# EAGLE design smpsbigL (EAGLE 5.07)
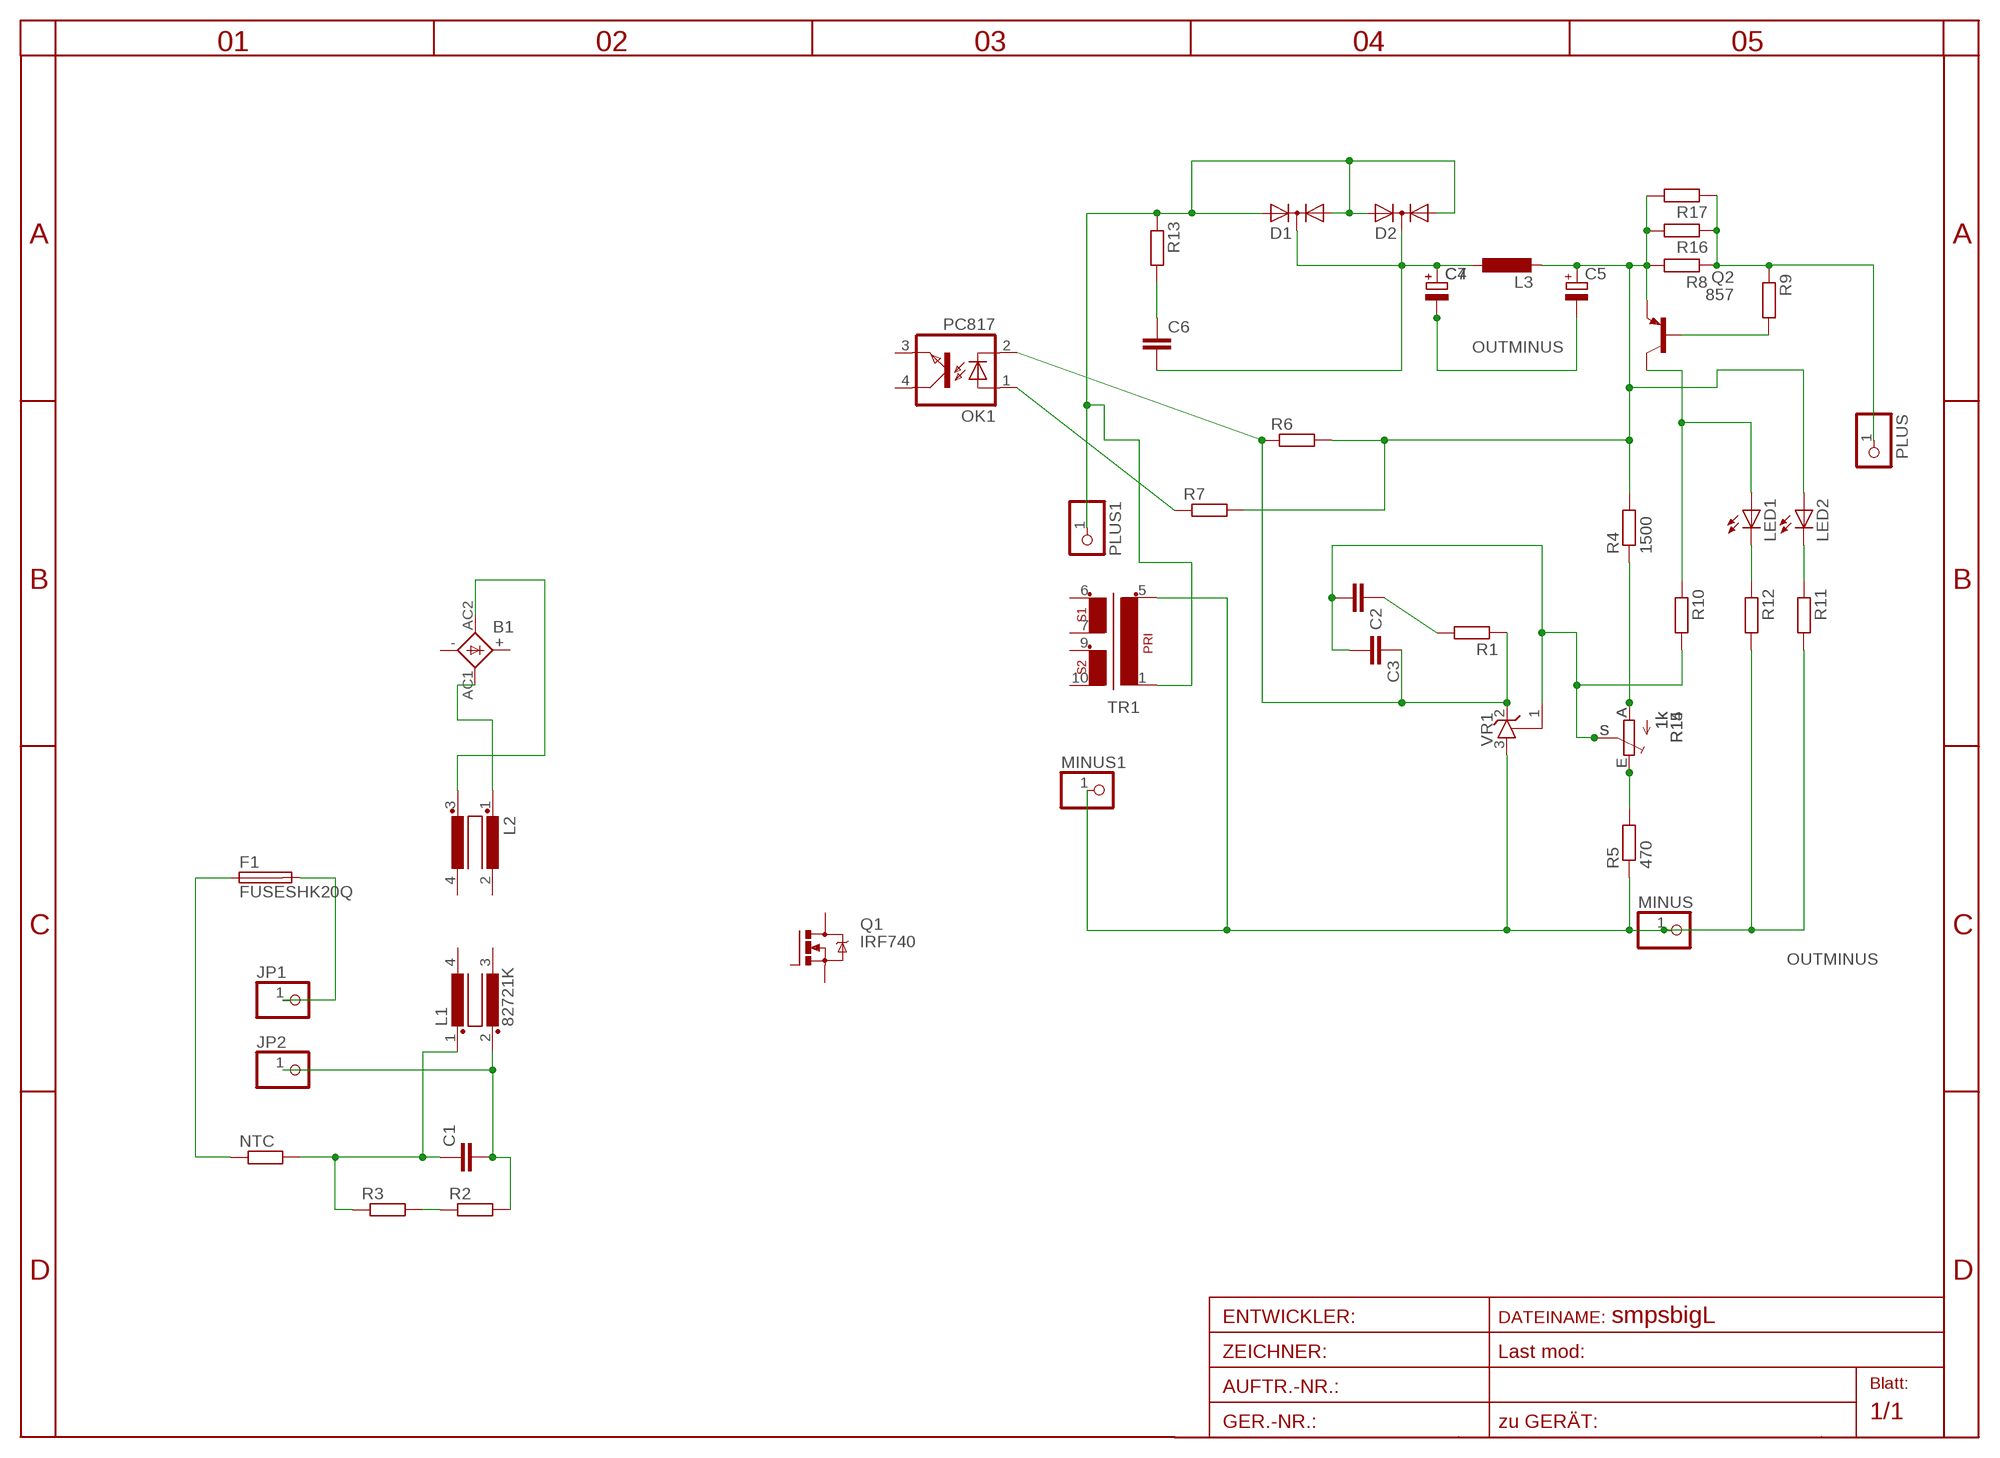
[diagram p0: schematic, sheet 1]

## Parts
B1  KBL  [KBL]
C1  C-EU150-084X183  [C150-084X183]
C2  C-EUC0805  [C0805]
C3  C-EUC0805  [C0805]
C4  CPOL-EUE5-8.5  [E5-8,5]
C5  CPOL-EUE5-8.5  [E5-8,5]
C6  C-EUC1206  [C1206]
C7  CPOL-EUE2.5-7  [E2,5-7]
D1  DIODE-2AC|CAIW220V  [IW220ABS]
D2  DIODE-2AC|CAIW220V  [IW220ABS]
F1  FUSESHK20Q  [SHK20Q]
JP1  PINHD-1X12MM2  [1X2MM2]
JP2  PINHD-1X12MM2  [1X2MM2]
L1  82721K  [82721K]
L2  R1405VB1  [B1]
L3  L-EUOPEN  [OPEN5]
LED1  LED3MM  [LED3MM]
LED2  LED3MM  [LED3MM]
MINUS  PINHD-1X12MM2  [1X2MM2]
MINUS1  PINHD-1X11X0.4  [1X01]
NTC  R-EU_0204/7  [0204/7]
OK1  PC817  [DIL04]
PLUS  PINHD-1X12MM2  [1X2MM2]
PLUS1  PINHD-1X11X0.4  [1X01]
Q1  IRF740  [TO220BV]
Q2  857  BC857ASMD  [SOT23-BEC]
R1  R-EU_R0805  [R0805]
R2  R-EU_R1206  [R1206]
R3  R-EU_R1206  [R1206]
R4  1500  R-EU_R0805  [R0805]
R5  470  R-EU_R0805  [R0805]
R6  R-EU_R0805  [R0805]
R7  R-EU_R0805  [R0805]
R8  R-EU_R3216  [R3216]
R9  R-EU_R0805  [R0805]
R10  R-EU_R0805  [R0805]
R11  R-EU_R0805  [R0805]
R12  R-EU_R0805  [R0805]
R13  R-EU_R1206  [R1206]
R14  1k  TRIM_EU-S64W  [S64W]
R15  1k  TRIM_EU-CA6V  [CA6V]
R16  R-EU_R2010  [R2010]
R17  R-EU_R1206  [R1206]
TR1  EE20-2  [EE30GREEN]
VR1  TL431CLPSOT23  [SOT23]

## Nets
A: R4.1 R14.A R15.A
C1: LED1.A Q2.C R10.1
CPLUS: C4.+ C6.2 C7.+ D1.C D2.C L3.1
E: R5.2 R14.E R15.E
N$1: C1.2 JP2.1 L1.2 R2.2
N$2: C1.1 L1.1 NTC.2 R3.1
N$3: F1.2A JP1.1
N$6: R2.1 R3.2
N$7: B1.AC2(AC1) L2.3
N$8: B1.AC1(AC2) L2.1
N$9: F1.1A NTC.1
N$11: C3.1 OK1.2(C) R1.1 R6.1 VR1.2(C)
N$12: OK1.1(A) R7.1
N$13: C2.1 R1.2
N$16: Q2.B R9.2
N$21: LED1.K(C) R12.1
N$23: LED2.K(C) R11.1
N$27: C6.1 R13.2
OUTMINUS: C4.- C5.- C7.- MINUS1.1 MINUS.1 R5.1 R11.2 R12.2 TR1.5 VR1.3(A)
OUTPLUS: PLUS.1 R8.1 R9.1 R16.1 R17.1
PLUS2: C5.+ L3.2 LED2.A Q2.E R4.2 R6.2 R7.2 R8.2 R16.2 R17.2
S: C2.2 C3.2 R10.2 R14.S R15.S VR1.1(R)
TOUT: D1.A1 D1.A2 D2.A1 D2.A2 PLUS1.1 R13.1 TR1.1
Unconnected: B1.+ B1.- L1.3 L1.4 L2.2 L2.4 OK1.3(EMIT) OK1.4(COL) Q1.D Q1.G Q1.S TR1.6 TR1.7 TR1.9 TR1.10

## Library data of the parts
B1 = rectifier:KBL: DIOTEC RECTIFIER
C1-C3 C6 = rcl:C-EU: CAPACITOR, European symbol
C4 C5 C7 = rcl:CPOL-EU: POLARIZED CAPACITOR, European symbol
D1 D2 = diode:DIODE-2AC|CA: Dual DIODE Anode-Cathode|Cathode-Anode
F1 = fuse:FUSE: Fuse
JP1 JP2 MINUS MINUS1 PLUS PLUS1 = pinhead:PINHD-1X1: PIN HEADER
L1 = inductors:82721K: FILTER
L2 = inductor-nkl:R1405V: Übertrager (verlustarm) bis typ. 400kHz Power transformer (low loss) up to typ. 400kHz
L3 = rcl:L-EU: INDUCTOR, European symbol
LED1 LED2 = led:LED: LED
NTC R1-R13 R16 R17 = rcl:R-EU_: RESISTOR, European symbol
OK1 = optocoupler:PC817: SHARP OPTO COUPLER
Q1 = transistor-power:IRF740: N-CHANNEL MOS FET
Q2 = transistor-pnp:BC857*: PNP Transistror
R14 R15 = pot:TRIM_EU-: POTENTIOMETER
TR1 = trafo:EE20-2: TRANSFORMER 1 primary winding, 2 secondary windings ERA
VR1 = v-reg:TL431CLP: VOLTAGE REGULATOR

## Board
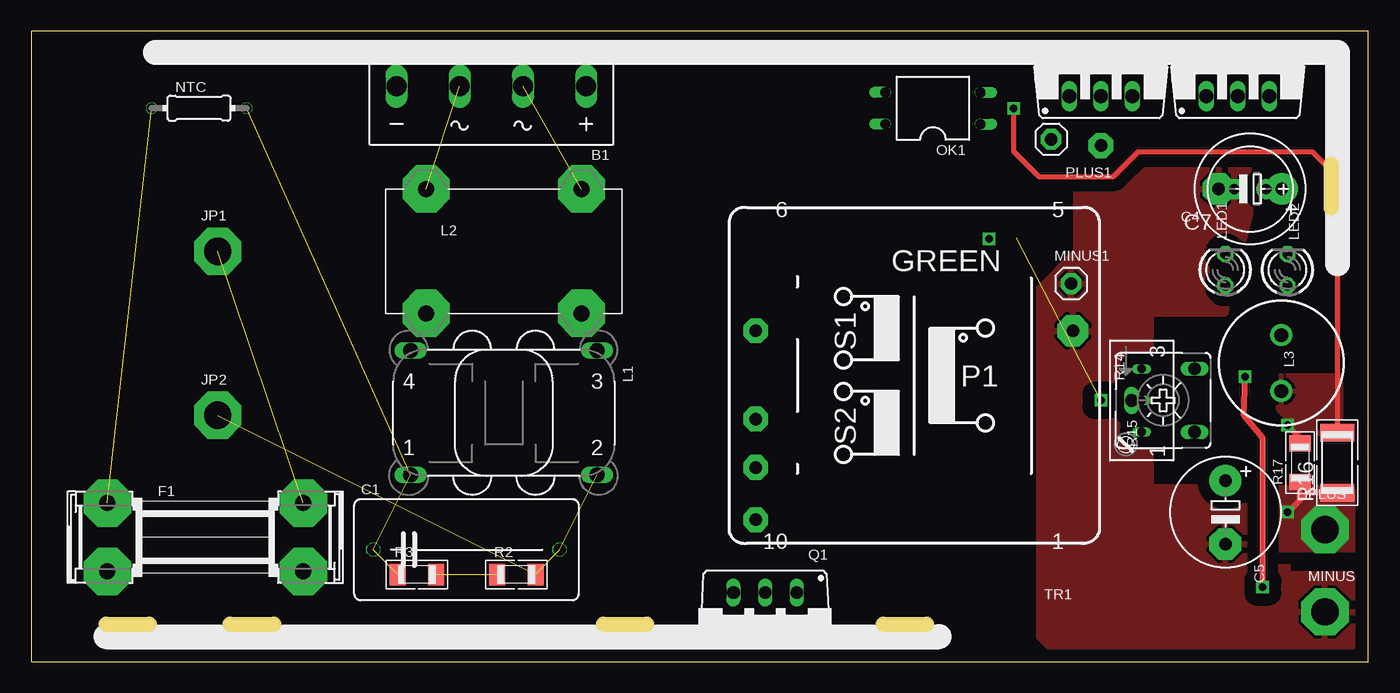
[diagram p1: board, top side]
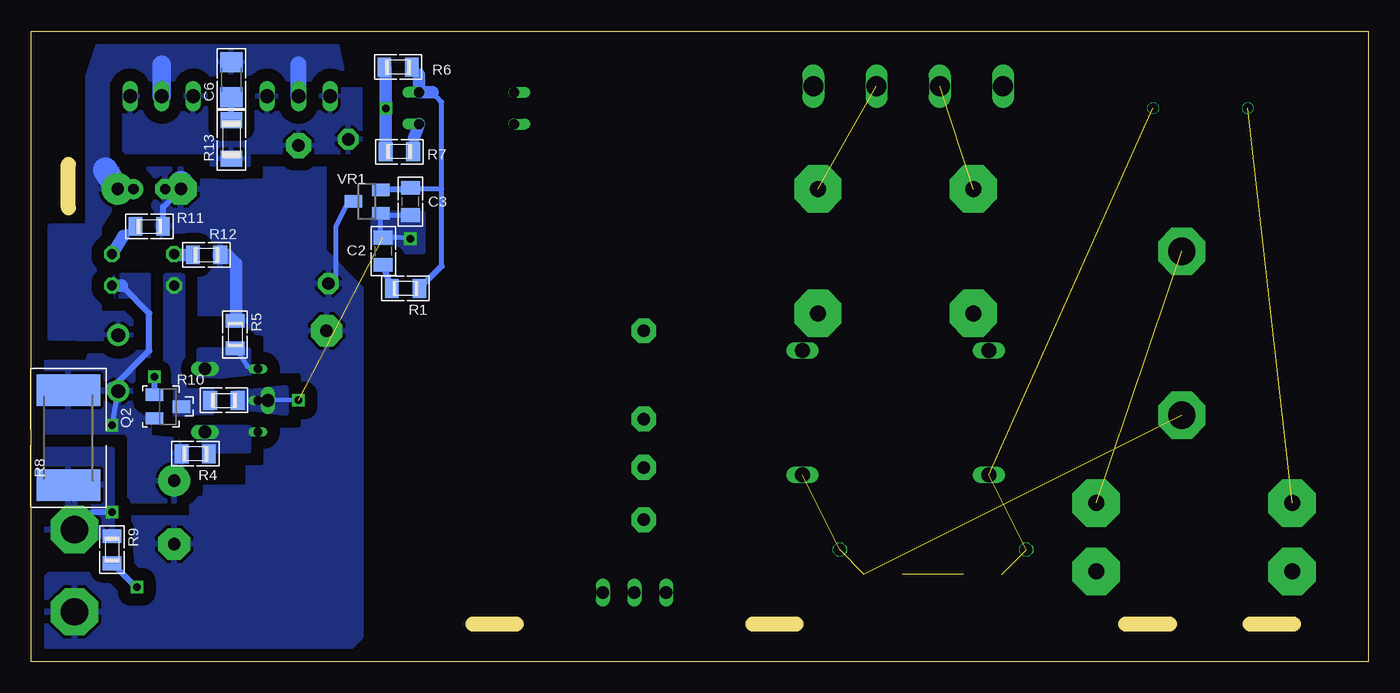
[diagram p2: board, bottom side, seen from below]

Size 107.5 x 50.7 mm. Coordinates in mm from the lower left corner, seen from the top.
Outline: 0,0 107.5,0 107.5,50.7 0,50.7 0,0
Copper layers (1*16): Top 0.035mm / dielectric 1.5mm / Bottom 0.035mm
Design rules "default": minimum track width 10mil, minimum drill 20mil, track to track 8mil, track to pad 8mil, pad to pad 8mil, via to via 8mil, smd to smd 8mil, copper to edge 40mil, drill to drill 8mil, minimum pad ring 1mil, minimum via ring 8mil, stop-mask expansion 4mil, vias tented up to drill 0mil, thermal gap 10mil
Milling: 5 lines

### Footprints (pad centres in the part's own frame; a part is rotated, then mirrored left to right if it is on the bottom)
KBL = drill 1.6 long: + -7.62,-1.27; - 7.62,-1.27; AC1 2.54,-1.27; AC2 -2.54,-1.27
C150-084X183 = drill 1.016 octagon: 1 -7.493,0; 2 7.493,0
C0805 = smd 1.1 x 1.5: 1 -1.1,0; 2 1.1,0
E5-8,5 = drill 1 pad 2.54 round: + -2.54,0 | drill 1 pad 2.54 octagon: - 2.54,0
C1206 = smd 1.6 x 1.8: 1 -1.4,0; 2 1.4,0
E2,5-7 = drill 0.813 pad 1.6 round: + -1.27,0 | drill 0.813 pad 1.6 octagon: - 1.27,0
IW220ABS = drill 1.118 long: A1 -2.54,-2.54; A2 2.54,-2.54; C 0,-2.54
SHK20Q = drill 1.3 pad 3.81 octagon: 1A -7.874,2.75; 1B -7.874,-2.75; 2A 7.874,2.75; 2B 7.874,-2.75
1X2MM2 = drill 2.2 pad 3.81 octagon: 1 0,0
82721K = drill 1.194 long: 1 7.493,5.004; 2 -7.493,5.004; 3 -7.493,-5.004; 4 7.493,-5.004
B1 = drill 1.27 pad 3.81 octagon: 1 -6.25,5; 2 -6.25,-5; 3 6.25,5; 4 6.25,-5
OPEN5 = drill 1.1 pad 1.778 round: 1 -2.25,0; 2 2.25,0
LED3MM = drill 0.8 pad 1.27 octagon: A -1.27,0; K 1.27,0
1X01 = drill 1 pad 1.676 octagon: 1 0,0
0204/7 = drill 0.813 octagon: 1 -3.81,0; 2 3.81,0
DIL04 = drill 0.813 offset: 1 -1.27,-3.81; 2 1.27,-3.81; 3 1.27,3.81; 4 -1.27,3.81
TO220BV = drill 1.016 long: D 0,-2.54; G -2.54,-2.54; S 2.54,-2.54
SOT23-BEC = smd 1 x 1.4: B -0.95,-1.1; C 0,1.1; E 0.95,-1.1
R0805 = smd 1.1 x 1.5: 1 -1.1,0; 2 1.1,0
R1206 = smd 1.3 x 1.7: 1 -1.55,0; 2 1.55,0
R3216 = smd 2.54 x 5.08: 1 -3.81,0; 2 3.81,0
S64W = drill 0.7 long: A 2.54,1.27; E -2.54,1.27; S 0,1.27
CA6V = drill 1.016 long: A -2.54,-2.54; E 2.54,-2.54; S 0,2.54
R2010 = smd 1.4 x 2.7: 1 -2.4,0; 2 2.4,0
EE30GREEN = drill 1 pad 2 octagon: 1 15,18.5; 6 -12.75,3.6; 7 -12.75,-3.5; 9 -12.75,-7.4; 10 -12.75,-11.6 | drill 1 pad 2.5 octagon: 5 12.75,3.6
SOT23 = smd 1 x 1.4: 1 -0.95,-1.1; 2 0.95,-1.1; 3 0,1.1

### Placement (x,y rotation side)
B1  37,45 180 top
C1  35,9 0 top
C2  79.2,33 90 bottom
C3  77,37 270 bottom
C4  98,38 180 top
C5  96,12 270 top
C6  91.4,46.8 90 bottom
C7  98,38 180 top
D1  97,48 0 top
D2  86,48 0 top
F1  14,10 0 top
JP1  15,33 0 top
JP2  15,19.8 0 top
L1  38,20 180 top
L2  38,33 0 top
L3  100.5,24 270 top
LED1  96,31.5 90 top
LED2  101,31.5 90 top
MINUS  104,4 0 top
MINUS1  83.6,30.4 0 top
NTC  13.5,44.5 0 top
OK1  72.5,44.5 90 top
PLUS  104,10.6 0 top
PLUS1  82,42 0 top
Q1  59,3 180 top
Q2  96.5,20.5 270 bottom
R1  77.4,30 180 bottom
R2  39,7 0 top
R3  31,7 0 top
R4  94.3,16.7 180 bottom
R5  91.1,26.3 270 bottom
R6  78,47.8 180 bottom
R7  77.9,41 180 bottom
R8  104.5,18 90 bottom
R9  101,9 270 bottom
R10  92,21 0 bottom
R11  98,35 0 bottom
R12  93.4,32.7 0 bottom
R13  91.4,42 90 bottom
R14  88,21 270 top
R15  91,21 90 top
R16  105,16 90 top
R17  102,16 90 top
TR1  71,23 0 top
VR1  80.5,37 90 bottom

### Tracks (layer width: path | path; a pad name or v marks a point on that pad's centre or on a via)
A
  pour Bottom (isolate 1.016, rank 2, no thermals): 90,18.8 94.2,18.8 94.2,16.9 90,17
C1
  pour Bottom (isolate 0.8, rank 3, no thermals): 95.3,31 96.7,31 96.7,19.9 93,20 93,22 95.3,22
CPLUS
  Bottom 1.27: D2.C 86,48
  Bottom 1.5: D1.C 97,48
  Bottom 2: C4.+ 101.54,39.54
  pour Bottom (isolate 1, rank 3): 83,50 102,50 103,47 103,35 106,35 106,26 99.4,25.9 99.4,28 102,28 102,31 102,35 100,38 101.1,45.8 82.1,45.8
E
  Bottom 0.406: R5.2 90.1,23.71 R14.E
  pour Bottom (isolate 1, rank 2, no thermals): 94,23 90,23 90,25 94,25
N$1  (3 unrouted)
N$2  (3 unrouted)
N$3  (1 unrouted)
N$6  (1 unrouted)
N$7  (1 unrouted)
N$8  (1 unrouted)
N$9  (1 unrouted)
N$11
  Bottom 0.406: 77.15,37.95 C3.1 76.9,38 74.5,38 | 74.5,31.8 74.5,38 | 76.31,47.21 R6.1 | 75.23,45.77 74.5,45 74.5,38
  Bottom 0.5: 77.15,37.95 VR1.2 | R1.1 74.5,31.8
  Bottom 1: 76.31,47.21 OK1.2 75.23,45.77
N$12
  Bottom 0.5: R7.1 76.7,42.14
  Bottom 1: 76.7,42.14 OK1.1
N$13
  Bottom 0.5: R1.2 C2.1
N$16  (via drill 0.6)
  Top 0.5: v97.6,22.9 97.5,19.8 99,18 v99,6
  Bottom 0.5: v97.6,22.9 Q2.B | v99,6 99.1,6 R9.2
N$21
  Bottom 1.016: R12.1 95.93,32.7 LED1.K
N$23
  Bottom 0.5: 100.1,34.2 R11.1
  Bottom 1: LED2.K 100.1,34.2
N$27
  Bottom 0.5: R13.2 C6.1
OUTMINUS
  Bottom 0.406: VR1.3 82,37 83,35 83,31 MINUS1.1
  Bottom 0.5: R11.2 96.9,36.56 C4.-
  Bottom 1.016: R12.2 91.7,32.7 91,32 91,27.5 R5.1
  Bottom 2: C4.- 95.46,38.46
  pour Bottom (isolate 1, rank 5): 98,40 84,40 84,33 81,30 81,2 82,1 106,1 107,2 107,6 106,7 101,7 101,14 90,14 90,28 96,28 98,36
  pour Top (isolate 1, rank 5): 98,40 84,40 84,33 81,30 81,2 82,1 106,1 107,2 107,6 106,7 101,7 101,14 90,14 90,28 96,28 98,36
OUTPLUS  (via drill 0.6)
  Top 0.5: R17.1 102,13 v101,12 102.6,13.6 R16.1
  Bottom 0.5: v101,12 102.6,12 PLUS.1
  pour Bottom (isolate 1): 107,17 107,10 106,9 103,9 101,10 101,17
  pour Top (isolate 1, no thermals): 101,14 106,14 107,13 107,9 100,9 100,14
PLUS2  (via drill 0.6)
  Top 0.406: R17.2 102,18 v101,19 | R16.2 105,39 103,41 89,41 87,39 81,39 R7.2 v79,44.5
  Bottom 0.406: 79,47.7 R6.2 | v101,19 L3.2 | v79,44.5 79,48
  Bottom 0.5: 100.23,30.23 98,28 98,25 101,22
  Bottom 1: R7.2 v79,44.5 79,47.7 | 100.23,30.23 LED2.A | L3.2 101,22
  pour Bottom (isolate 1, rank 4): 103,24 107,24 107,17 100,13 95,13 94.7,17.7 98,18 98,31 100.7,31
  pour Top (isolate 2): 100,23 106,23 106,19 105,18 100,18
S  (via drill 0.6)  (1 unrouted)
  Bottom 0.406: C3.2 79.25,35.9 VR1.1 79.4,34.3 C2.2 77.9,34.1 v77,34 | v86,21 87.9,21.04 R15.S
  pour Bottom (isolate 1, no thermals): 87,22 91.4,21.5 91.4,20.6 87,20
  pour Bottom (isolate 1, rank 3, no thermals): 76,36 80,36 80,33 76,33
TOUT
  pour Bottom (isolate 1, rank 2): 81,46 100,46 100,41 93,41 93,40 90,40 90,41 81,41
